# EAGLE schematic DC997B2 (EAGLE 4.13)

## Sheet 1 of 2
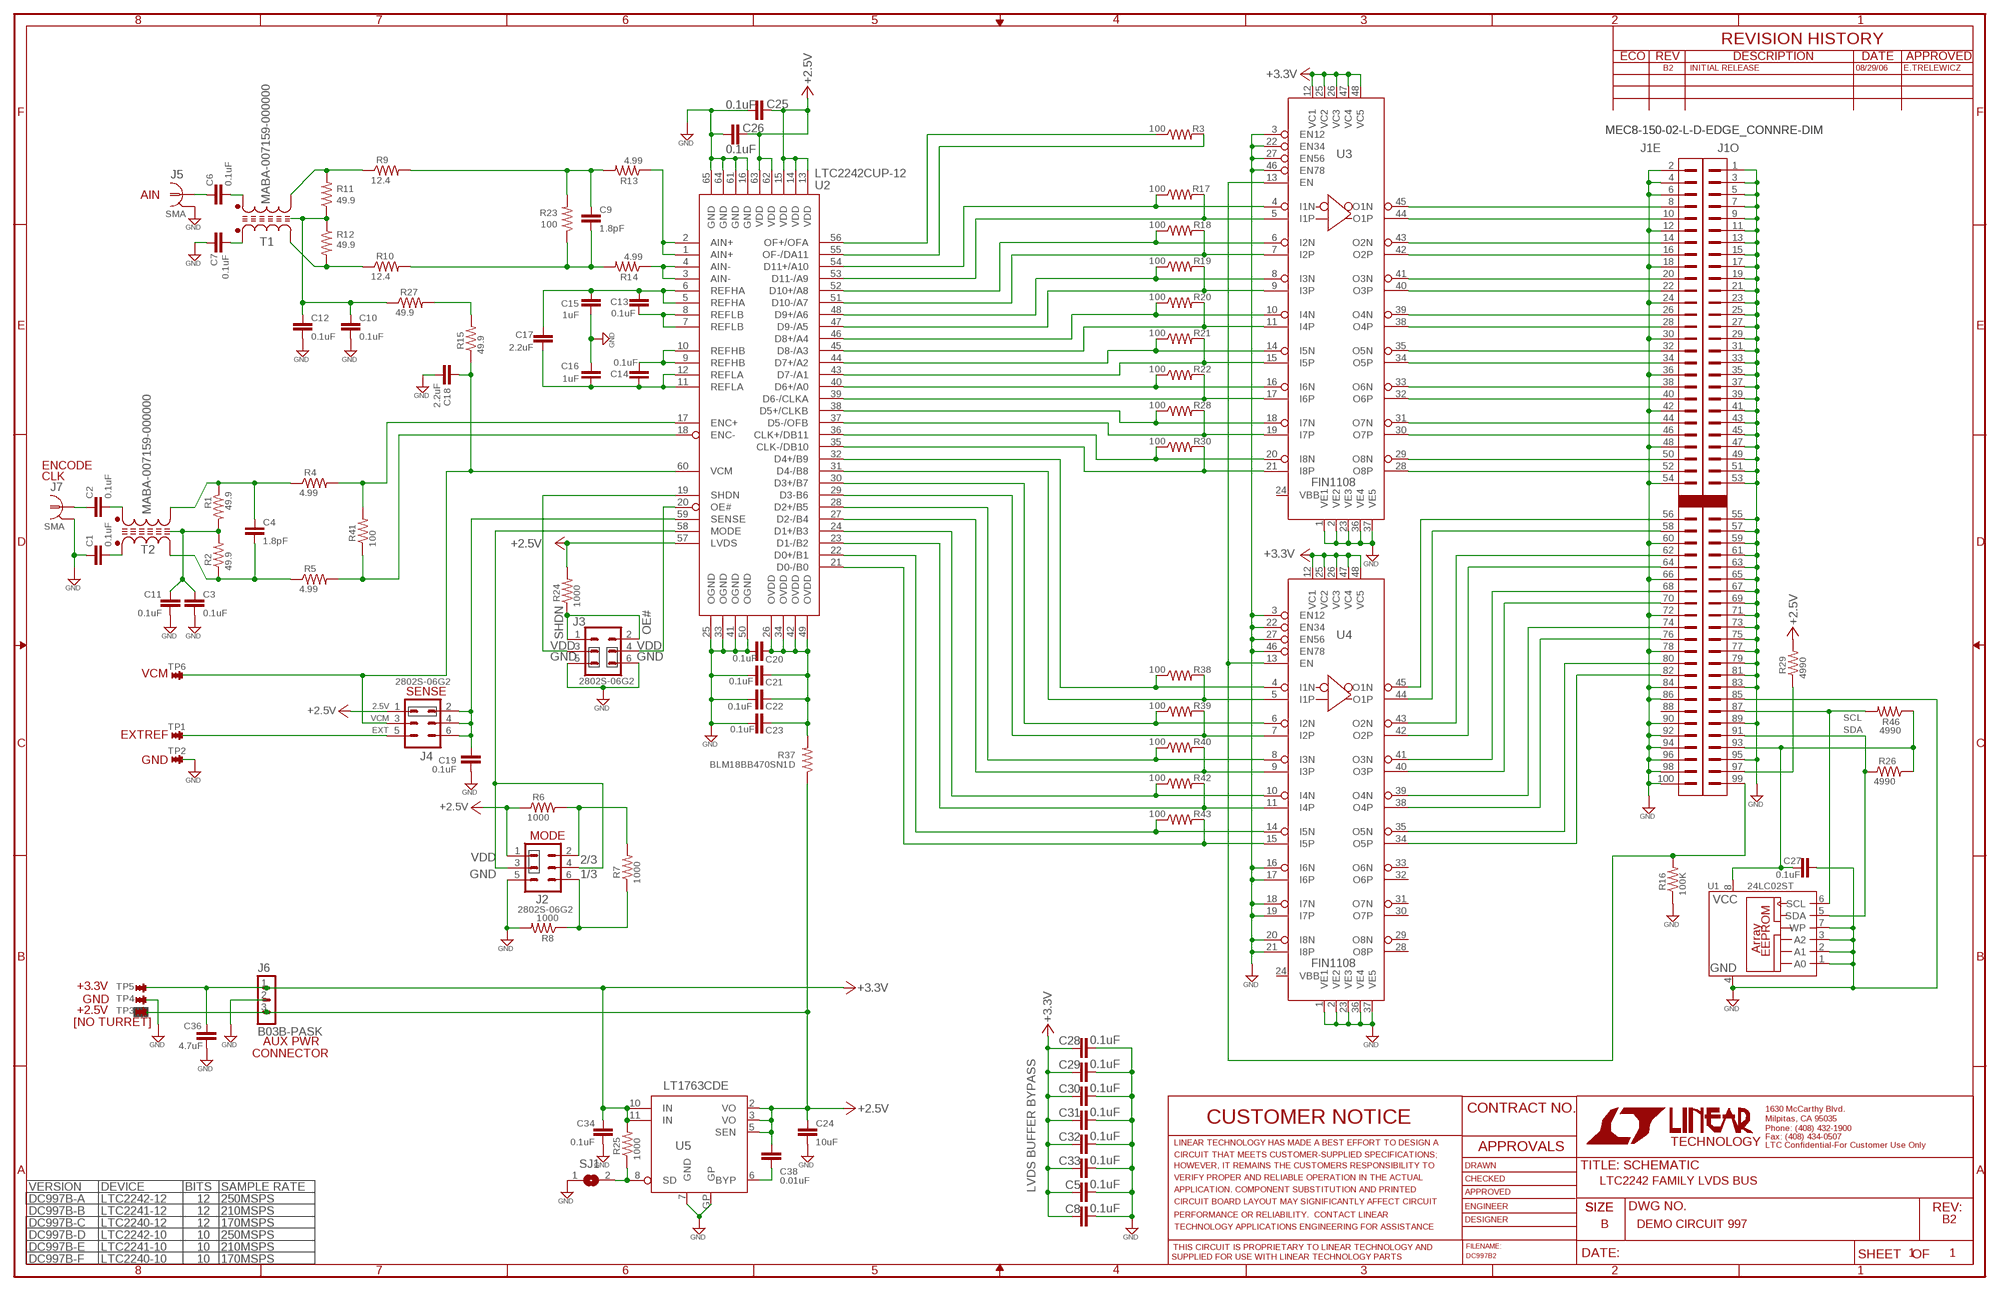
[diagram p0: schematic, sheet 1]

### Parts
C1  0.1uF  CAP-NP-SMT-C0402  [C0402]
C2  0.1uF  CAP-NP-SMT-C0402  [C0402]
C3  0.1uF  CAP-NP-SMT-C0603  [C0603]
C4  1.8pF  CAP-NP-SMT-C0402  [C0402]
C5  0.1uF  CAP-NP-SMT-C0402  [C0402]
C6  0.1uF  CAP-NP-SMT-C0402  [C0402]
C7  0.1uF  CAP-NP-SMT-C0402  [C0402]
C8  0.1uF  CAP-NP-SMT-C0402  [C0402]
C9  1.8pF  CAP-NP-SMT-C0402  [C0402]
C10  0.1uF  CAP-NP-SMT-C0402  [C0402]
C11  0.1uF  CAP-NP-SMT-C0603  [C0603]
C12  0.1uF  CAP-NP-SMT-C0402  [C0402]
C13  0.1uF  CAP-NP-SMT-C0402  [C0402]
C14  0.1uF  CAP-NP-SMT-C0402  [C0402]
C15  1uF  CAP-NP-SMT-C0603  [C0603]
C16  1uF  CAP-NP-SMT-C0603  [C0603]
C17  2.2uF  CAP-NP-SMT-C0603  [C0603]
C18  2.2uF  CAP-NP-SMT-C0603  [C0603]
C19  0.1uF  CAP-NP-SMT-C0402  [C0402]
C20  0.1uF  CAP-NP-SMT-C0402  [C0402]
C21  0.1uF  CAP-NP-SMT-C0402  [C0402]
C22  0.1uF  CAP-NP-SMT-C0402  [C0402]
C23  0.1uF  CAP-NP-SMT-C0402  [C0402]
C24  10uF  CAP-NP-SMT-C1206  [C1206]
C25  0.1uF  CAP-NP-SMT-C0402  [C0402]
C26  0.1uF  CAP-NP-SMT-C0402  [C0402]
C27  0.1uF  CAP-NP-SMT-C0402  [C0402]
C28  0.1uF  CAP-NP-SMT-C0402  [C0402]
C29  0.1uF  CAP-NP-SMT-C0402  [C0402]
C30  0.1uF  CAP-NP-SMT-C0402  [C0402]
C31  0.1uF  CAP-NP-SMT-C0402  [C0402]
C32  0.1uF  CAP-NP-SMT-C0402  [C0402]
C33  0.1uF  CAP-NP-SMT-C0402  [C0402]
C34  0.1uF  CAP-NP-SMT-C0603  [C0603]
C36  4.7uF  CAP-NP-SMT-C0805  [C0805]
C38  0.01uF  CAP-NP-SMT-C0402  [C0402]
J1  MEC8-150-02-L-D-EDGE_CONNRE-DIM  [MEC8-150-02-L-D-EDGE_CONN-NEW-ORIGIN]
J2  2802S-06G2  HDR-3X2-PS2MM  [HDR-3X2PS-2MM]
J3  2802S-06G2  HDR-3X2-PS2MM  [HDR-3X2PS-2MM]
J4  2802S-06G2  HDR-3X2-PS2MM  [HDR-3X2PS-2MM]
J5  SMA  RF_CONN-SMA-FEMALE-EDGE-MNT  [SMA-FEMALE-EDGE-MNT]
J6  B03B-PASK  JMPR-3X1-PS2MM  [HDR-3X1PS-2MM]
J7  SMA  RF_CONN-SMA-FEMALE-EDGE-MNT  [SMA-FEMALE-EDGE-MNT]
R1  49.9  RES-R0402  [R0402]
R2  49.9  RES-R0402  [R0402]
R3  100  RES-R0201  [R0201]
R4  4.99  RES-R0402  [R0402]
R5  4.99  RES-R0402  [R0402]
R6  1000  RES-R0603  [R0603]
R7  1000  RES-R0603  [R0603]
R8  1000  RES-R0603  [R0603]
R9  12.4  RES-R0402  [R0402]
R10  12.4  RES-R0402  [R0402]
R11  49.9  RES-R0402  [R0402]
R12  49.9  RES-R0402  [R0402]
R13  4.99  RES-R0402  [R0402]
R14  4.99  RES-R0402  [R0402]
R15  49.9  RES-R0402  [R0402]
R16  100K  RES-R0402  [R0402]
R17  100  RES-R0201  [R0201]
R18  100  RES-R0201  [R0201]
R19  100  RES-R0201  [R0201]
R20  100  RES-R0201  [R0201]
R21  100  RES-R0201  [R0201]
R22  100  RES-R0201  [R0201]
R23  100  RES-R0402  [R0402]
R24  1000  RES-R0402  [R0402]
R25  1000  RES-R0603  [R0603]
R26  4990  RES-R0402  [R0402]
R27  49.9  RES-R0402  [R0402]
R28  100  RES-R0201  [R0201]
R29  4990  RES-R0402  [R0402]
R30  100  RES-R0201  [R0201]
R37  BLM18BB470SN1D  RES-R0603  [R0603]
R38  100  RES-R0201  [R0201]
R39  100  RES-R0201  [R0201]
R40  100  RES-R0201  [R0201]
R41  100  RES-R0201  [R0201]
R42  100  RES-R0201  [R0201]
R43  100  RES-R0201  [R0201]
R46  4990  RES-R0402  [R0402]
SJ1  SJ  [SJ]
T1  MABA-007159-000000  ETC1-1-13  [MACOM_ETC1-XFMR]
T2  MABA-007159-000000  ETC1-1-13  [MACOM_ETC1-XFMR]
TP1  TURRET0.063  [TURRET_MILLMAX_2308-2]
TP2  TURRET0.063  [TURRET_MILLMAX_2308-2]
TP3  TURRET0.063  [TURRET_MILLMAX_2308-2]
TP4  TURRET0.063  [TURRET_MILLMAX_2308-2]
TP5  TURRET0.063  [TURRET_MILLMAX_2308-2]
TP6  TURRET0.063  [TURRET_MILLMAX_2308-2]
U1  24LC02ST  [TSSOP8]
U2  LTC2242CUP-12  LTC2242IUP  [QFN_9X9]
U3  FIN1108  [TSSOP48]
U4  FIN1108  [TSSOP48]
U5  LT1763CDE  [DE12]

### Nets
+2.5V: C24.1 C25.2 C26.2 C38.1 J2.1 J4.1 J6.3 R6.1 R24.2 R29.2 R37.1 TP3.1 U2.13(VDD) U2.14(VDD) U2.15(VDD) U2.57(LVDS) U2.62(VDD) U2.63(VDD) U5.2(VO) U5.3(VO) U5.5(SEN)
+3.3V: C5.1 C8.1 C28.1 C29.1 C30.1 C31.1 C32.1 C33.1 C34.1 C36.1 J6.1 R25.2 TP5.1 U3.12(VC1) U3.25(VC2) U3.26(VC3) U3.47(VC4) U3.48(VC5) U4.12(VC1) U4.25(VC2) U4.26(VC3) U4.47(VC4) U4.48(VC5) U5.10(IN) U5.11(IN)
AIN+: R13.1 U2.1(AIN+) U2.2(AIN+)
AIN-: R14.1 U2.3(AIN-) U2.4(AIN-)
EXT_REF: J4.5 TP1.1
GND: C1.1 C3.2 C5.2 C7.2 C8.2 C10.2 C11.2 C12.2 C15.2 C16.1 C18.2 C19.2 C20.2 C21.2 C22.2 C23.2 C24.2 C25.1 C26.1 C27.2 C28.2 C29.2 C30.2 C31.2 C32.2 C33.2 C34.2 C36.2 J1.1 J1.2 J1.3 J1.4 J1.5 J1.6 J1.7 J1.9 J1.11 J1.12 J1.13 J1.15 J1.17 J1.18 J1.19 J1.21 J1.23 J1.24 J1.25 J1.27 J1.29 J1.30 J1.31 J1.33 J1.35 J1.36 J1.37 J1.39 J1.41 J1.42 J1.43 J1.45 J1.47 J1.48 J1.49 J1.51 J1.53 J1.54 J1.55 J1.57 J1.59 J1.60 J1.61 J1.63 J1.65 J1.66 J1.67 J1.69 J1.71 J1.72 J1.73 J1.75 J1.77 J1.78 J1.79 J1.81 J1.83 J1.84 J1.85 J1.86 J1.89 J1.90 J1.92 J1.94 J1.95 J1.96 J1.98 J1.100 J2.5 J3.5 J3.6 J5.2(GND) J6.2 J7.2(GND) R8.2 R16.1 SJ1.1 TP2.1 TP4.1 U1.1(A0) U1.2(A1) U1.3(A2) U1.4(GND) U1.7(WP) U2.16(GND) U2.25(OGND) U2.33(OGND) U2.41(OGND) U2.50(OGND) U2.61(GND) U2.64(GND) U2.65(GND) U3.1(VE1) U3.2(VE2) U3.3(EN12) U3.22(EN34) U3.23(VE3) U3.27(EN56) U3.36(VE4) U3.37(VE5) U3.46(EN78) U4.1(VE1) U4.2(VE2) U4.3(EN12) U4.16(I6N) U4.17(I6P) U4.18(I7N) U4.19(I7P) U4.20(I8N) U4.21(I8P) U4.22(EN34) U4.23(VE3) U4.27(EN56) U4.36(VE4) U4.37(VE5) U4.46(EN78) U5.7(GND) U5.GP ; also sheet 2
ISOVCM: C10.1 C12.1 R11.1 R12.1 R27.1
MODE: J2.3 J2.4 U2.58(MODE)
N$1: C2.2 T2.4
N$2: C1.2 T2.5
N$3: C3.1 C11.1 R1.2 R2.2
N$4: C2.1 J7.1
N$6: C4.2 R2.1 R5.1 T2.1
N$7: C4.1 R1.1 R4.1 T2.3
N$8: R4.2 R41.2 U2.17(ENC+)
N$9: R5.2 R41.1 U2.18(ENC-)
N$10: J2.2 R6.2 R7.2
N$11: J2.6 R7.1 R8.1
N$12: J3.4 U2.20(OE#)
N$13: C7.1 T1.4
N$14: C13.2 C15.1 C17.1 U2.5(REFHA) U2.6(REFHA)
N$15: C13.1 U2.7(REFLB) U2.8(REFLB)
N$16: R39.1 U2.30(D3+/B7) U4.6(I2N)
N$17: R9.1 R11.2 T1.1
N$18: C14.2 U2.9(REFHB) U2.10(REFHB)
N$19: R10.1 R12.2 T1.3
N$20: C9.1 R9.2 R13.2 R23.2
N$21: J1.8 U3.45(O1N)
N$22: C9.2 R10.2 R14.2 R23.1
N$23: J1.56 U4.45(O1N)
N$24: R15.2 R27.2
N$25: C14.1 C16.2 C17.2 U2.11(REFLA) U2.12(REFLA)
N$27: J1.58 U4.44(O1P)
N$28: J1.62 U4.43(O2N)
N$29: J1.80 U4.35(O5N)
N$30: J1.82 U4.34(O5P)
N$31: J1.10 U3.44(O1P)
N$32: R3.2 U2.55(OF-/DA11)
N$33: R17.1 U2.54(D11+/A10) U3.4(I1N)
N$34: J1.14 U3.43(O2N)
N$35: R17.2 U2.53(D11-/A9) U3.5(I1P)
N$36: J1.16 U3.42(O2P)
N$37: R3.1 U2.56(OF+/OFA)
N$38: J3.1 J3.2 R24.1
N$39: R43.1 U2.22(D0+/B1) U4.14(I5N)
N$41: R25.1 SJ1.2 U5.8(SD)
N$44: R42.1 U2.24(D1+/B3) U4.10(I4N)
N$60: J1.20 U3.41(O3N)
N$62: J1.97 R29.1
N$63: J1.22 U3.40(O3P)
N$66: R18.1 U2.52(D10+/A8) U3.6(I2N)
N$67: R18.2 U2.51(D10-/A7) U3.7(I2P)
N$68: R19.1 U2.48(D9+/A6) U3.8(I3N)
N$69: R19.2 U2.47(D9-/A5) U3.9(I3P)
N$70: R20.1 U2.46(D8+/A4) U3.10(I4N)
N$71: R20.2 U2.45(D8-/A3) U3.11(I4P)
N$72: J1.26 U3.39(O4N)
N$73: J1.28 U3.38(O4P)
N$74: J1.32 U3.35(O5N)
N$75: J1.34 U3.34(O5P)
N$76: J1.38 U3.33(O6N)
N$77: J1.40 U3.32(O6P)
N$78: J1.44 U3.31(O7N)
N$79: J1.46 U3.30(O7P)
N$80: J1.50 U3.29(O8N)
N$81: J1.52 U3.28(O8P)
N$83: R30.2 U2.35(CLK-/DB10) U3.21(I8P)
N$84: R30.1 U2.36(CLK+/DB11) U3.20(I8N)
N$85: R21.1 U2.44(D7+/A2) U3.14(I5N)
N$86: R21.2 U2.43(D7-/A1) U3.15(I5P)
N$87: R22.1 U2.40(D6+/A0) U3.16(I6N)
N$88: R22.2 U2.39(D6-/CLKA) U3.17(I6P)
N$89: R28.1 U2.38(D5+/CLKB) U3.18(I7N)
N$90: R28.2 U2.37(D5-/OFB) U3.19(I7P)
N$91: J1.64 U4.42(O2P)
N$92: J1.68 U4.41(O3N)
N$93: J1.70 U4.40(O3P)
N$94: J1.74 U4.39(O4N)
N$95: J1.76 U4.38(O4P)
N$98: R38.1 U2.32(D4+/B9) U4.4(I1N)
N$99: R38.2 U2.31(D4-/B8) U4.5(I1P)
N$100: R39.2 U2.29(D3-B6) U4.7(I2P)
N$102: R40.1 U2.28(D2+/B5) U4.8(I3N)
N$103: R40.2 U2.27(D2-/B4) U4.9(I3P)
N$104: R42.2 U2.23(D1-/B2) U4.11(I4P)
N$106: R43.2 U2.21(D0-/B0) U4.15(I5P)
N$119: C6.1 J5.1
N$126: C38.2 U5.6(BYP)
N$137: C6.2 T1.5
OE: J1.99 R16.2 U3.13(EN) U4.13(EN)
OVDD: C20.1 C21.1 C22.1 C23.1 R37.2 U2.26(OVDD) U2.34(OVDD) U2.42(OVDD) U2.49(OVDD)
SCL: J1.87 R46.2 U1.6(SCL)
SDA: J1.91 R26.1 U1.5(SDA)
SENSE: C19.1 J4.2 J4.4 J4.6 U2.59(SENSE)
SHDN: J3.3 U2.19(SHDN)
VCM: C18.1 J4.3 R15.1 TP6.1 U2.60(VCM)
VROM: C27.1 J1.93 R26.2 R46.1 U1.8(VCC)
Unconnected: J1.88 U3.24(VBB) U4.24(VBB) U4.28(O8P) U4.29(O8N) U4.30(O7P) U4.31(O7N) U4.32(O6P) U4.33(O6N)

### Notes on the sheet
- B2 | INITIAL RELEASE | 08/29/06 | E.TRELEWICZ
- AIN
- ENCODE
- CLK
- OE#
- SHDN
- VDD | VDD
- GND | GND
- VCM
- SENSE
- 2.5V
- VCM
- EXT
- EXTREF
- GND
- MODE
- VDD | 2/3
- GND | 1/3
- +3.3V
- GND
- +2.5V
- [NO TURRET]
- AUX PWR
- CONNECTOR
- LTC2242 FAMILY LVDS BUS
- VERSION | DEVICE | BITS | SAMPLE RATE | LVDS BUFFER BYPASS
- DC997B-A | LTC2242-12 | 12 | 250MSPS
- DC997B-B | LTC2241-12 | 12 | 210MSPS
- B2
- DC997B-C | LTC2240-12 | 12 | 170MSPS | B | DEMO CIRCUIT 997
- DC997B-D | LTC2242-10 | 10 | 250MSPS
- DC997B-E | LTC2241-10 | 10 | 210MSPS
- 1 | 1
- DC997B-F | LTC2240-10 | 10 | 170MSPS

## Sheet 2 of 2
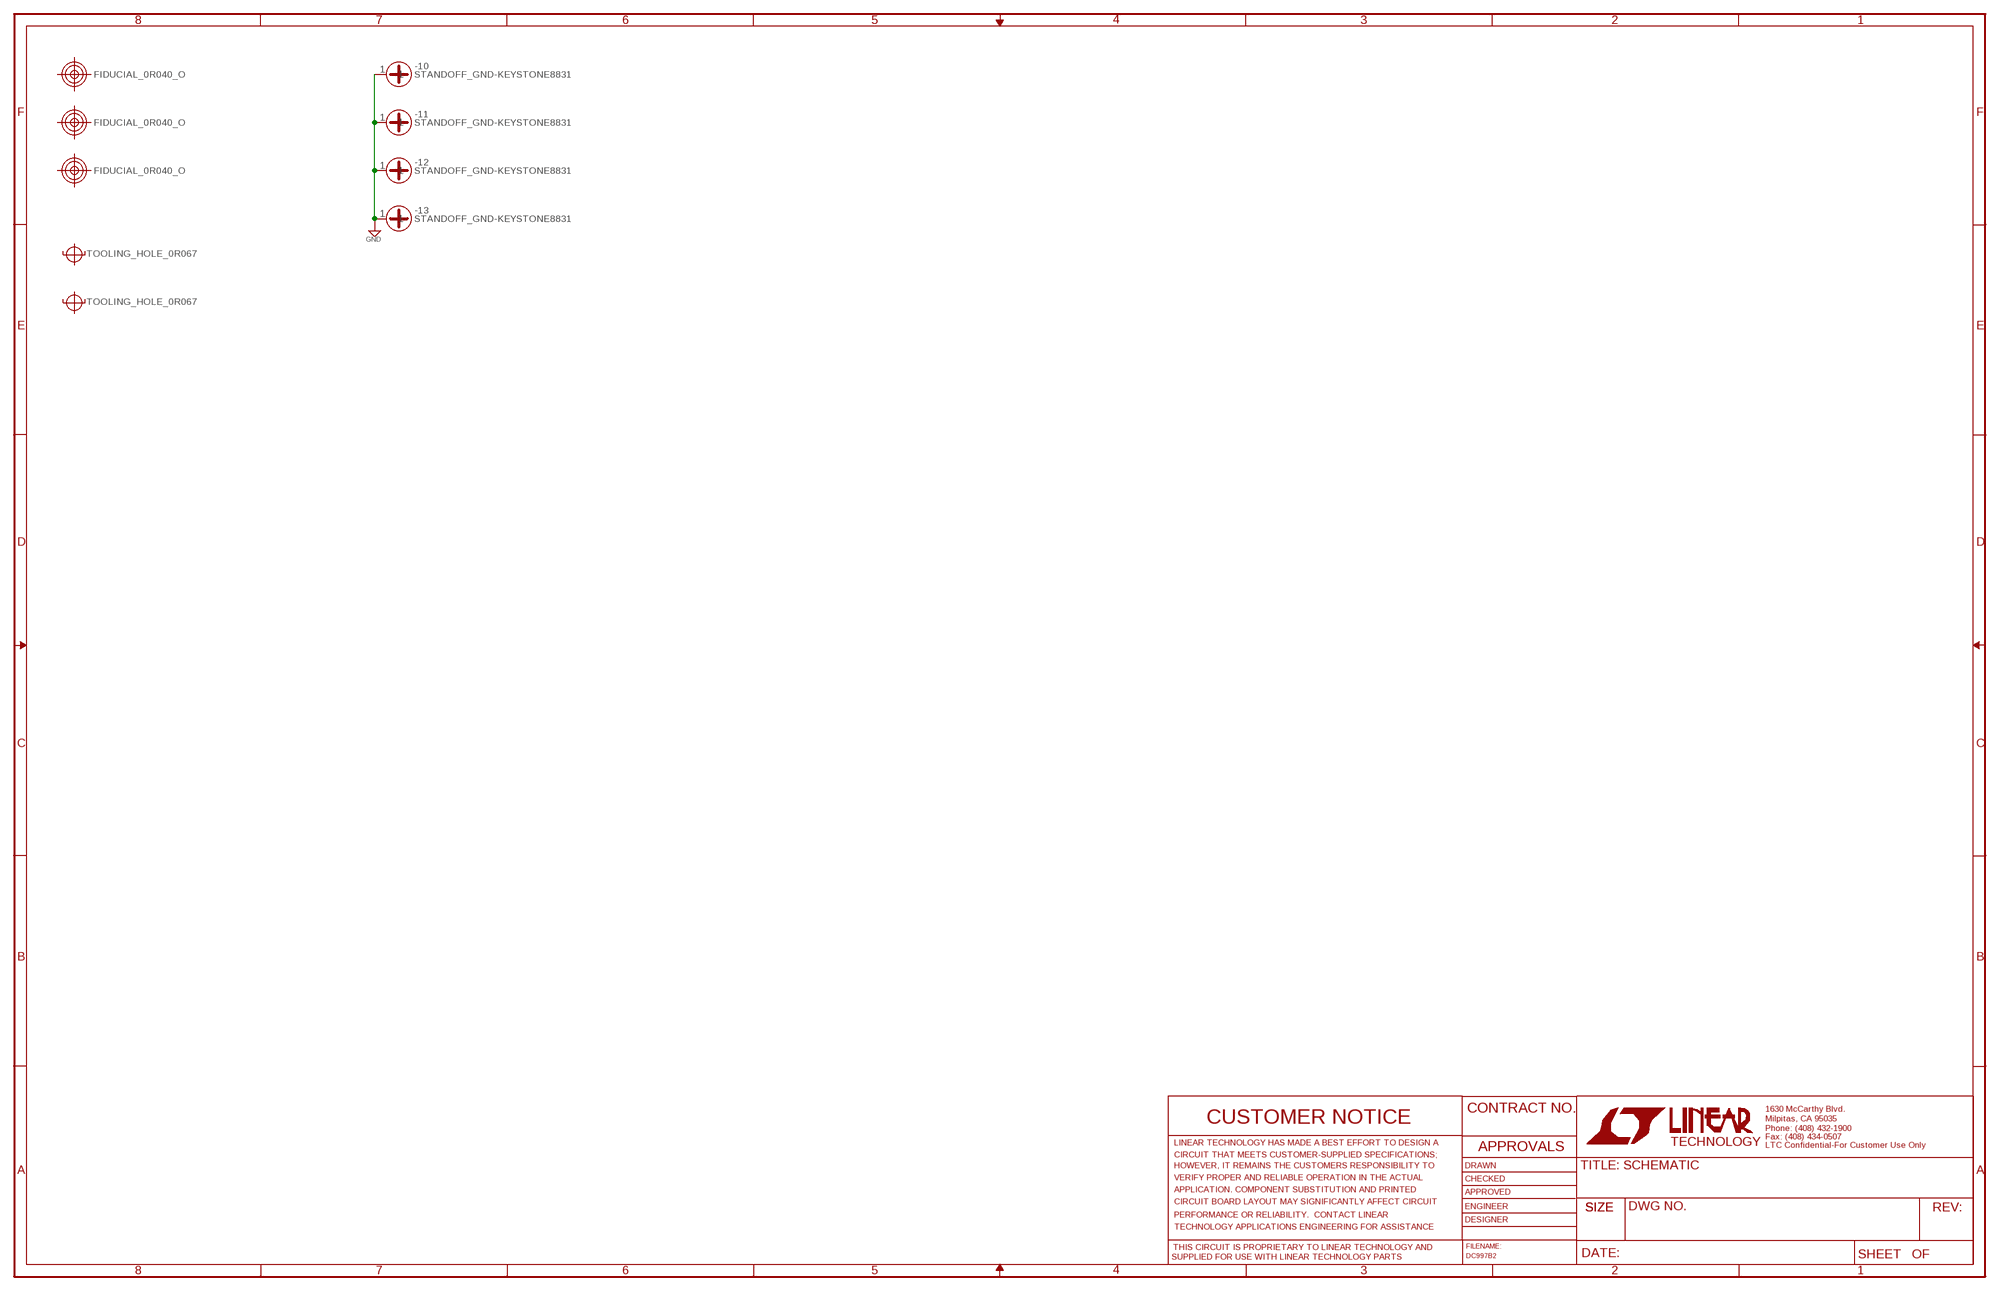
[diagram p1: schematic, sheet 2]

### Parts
-1  FIDUCIAL_0R040_O  [FIDUCIAL_0R040]
-2  FIDUCIAL_0R040_O  [FIDUCIAL_0R040]
-3  FIDUCIAL_0R040_O  [FIDUCIAL_0R040]
-8  TOOLING_HOLE_0R067  [TOOLING_HOLE_0R067]
-9  TOOLING_HOLE_0R067  [TOOLING_HOLE_0R067]
-10  STANDOFF_GND-KEYSTONE8831  [KEYSTONE_8831_GND]
-11  STANDOFF_GND-KEYSTONE8831  [KEYSTONE_8831_GND]
-12  STANDOFF_GND-KEYSTONE8831  [KEYSTONE_8831_GND]
-13  STANDOFF_GND-KEYSTONE8831  [KEYSTONE_8831_GND]

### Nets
GND: -10.1 -11.1 -12.1 -13.1 ; also sheet 1

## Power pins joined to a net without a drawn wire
GND: J5.3(GND) J5.4(GND) J5.5(GND) J7.3(GND) J7.4(GND) J7.5(GND)

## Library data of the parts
-1--3 = LTDB_Hardware:FIDUCIAL: Fiducials
-8 -9 = LTDB_Hardware:TOOLING_HOLE
-10--13 = LTDB_Hardware:STANDOFF_GND
C1-C34 C36 C38 = LTDB_Passives:CAP-NP-SMT-: Capacitor; Non-polar; SMT
J1 = LTDB_Connectors:MEC8-150-02-L-D-EDGE_CONN
J2-J4 = LTDB_Connectors:HDR-3X2-PS: Header 3x2 Pin, Straight
J5 J7 = LTDB_Connectors:RF_CONN-: BNC CONNECTOR M/A COM www.macom.com distributor Farnell 149-452
J6 = LTDB_Connectors:JMPR-3X1-PS: Jumper,3pin, point connections
R1-R30 R37-R43 R46 = LTDB_Passives:RES-: Resistor; GP
SJ1 = jumper:SJ: SMD solder JUMPER
T1 T2 = LTDB_Passives:ETC1-1-13: Balun 1:1, SMT, MaCom
TP1-TP6 = LTDB_Connectors:TURRET: Turret
U1 = LTDB_ICs:24*?: I2C SEEP Memory
U2 = LTDB_Linear_Parts:LTC2242*?: ADC,12Bit,250Msps
U3 U4 = LTDB_ICs:FIN1108*: REPEATER,OCTAL,LVDS
U5 = LTDB_Linear_Parts:LT1763CDE: LDO, SMT, DFN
